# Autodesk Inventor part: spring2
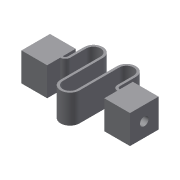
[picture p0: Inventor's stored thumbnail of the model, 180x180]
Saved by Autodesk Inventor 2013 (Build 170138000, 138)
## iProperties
Created: 2013-11
Part Number: spring2
Material: Generic
Document SubType Name: Modeling
Designer: Jonas
Density: 1 g/cm^3
Author: Jonas
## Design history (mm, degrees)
sketch "Sketch1"
  geometry: L1 (19, -5)-(10, -5); L2 (10, -5)-(10, 5); L3 (10, 5)-(19, 5); L4 (19, 5)-(19, -5); 2 further points
  constraints: 8 end point, 2 parallel, 1 horizontal, 1 horizontal alignment, 1 midpoint, 1 perpendicular
  dimensions: "d1" = 9 distance of L2.end L3.end; "d2" = 10 distance of L1.end L2.end; "d3" = 19 distance from line of L4 point (0, 0)
extrude "Extrusion1" new body sketch "Sketch1" distance "d4" = 10; taper "d5" = 0 deg
sketch "Sketch2"
  geometry: L1 (10, -5)-(19, -5) reference; L2 (19, -5)-(19, 5) reference; L3 (19, 5)-(10, 5) reference; L4 (10, 5)-(10, -5) reference; L5 (10, 0.4)-(10, -0.4); L6 (9.062, 1.338)-(9.062, 7); L7 (2.487, 7)-(2.487, -7); L8 (8.262, 1.338)-(8.262, 7); L9 (3.287, 7)-(3.287, -7); L10 (0, -10.287)-(0, -9.487); L11 (0, 0)-(0, 11.396); A1 r 0.938 centre (10, 1.338) between (9.062, 1.338) and (10, 0.4); A2 r 3.287 centre (5.775, 7) between (9.062, 7) and (2.487, 7); A3 r 2.487 centre (0, -7) between (0, -9.487) and (2.487, -7); A4 r 1.738 centre (10, 1.338) between (8.262, 1.338) and (10, -0.4); A5 r 2.487 centre (5.775, 7) between (8.262, 7) and (3.287, 7); A6 r 3.287 centre (0, -7) between (0, -10.287) and (3.287, -7); 3 further points
  constraints: 14 end point, 12 point on circle, 8 tangent, 6 centre point, 5 parallel, 4 coincident, 4 line through centre, 2 midpoint, 2 vertical, 1 collinear, 1 equal radius, 1 point on line, 1 vertical alignment, 1 other
  dimensions: "d6" = 0.8 distance of L5.start L5.end; "d11" = 7 vertical distance of A2.centre point (0, 0); "d12" = 7 distance of A3.centre point (0, 0) (= d11); "d14" = 0.8 distance between parallel lines of L6 L8
extrude "Extrusion2" join sketch "Sketch2" stored distance "d18" = 10; taper "d19" = 0 deg
sketch "Sketch3"
  geometry: C1 r 1.5 at (-5, 5); 1 further point
  constraints: 1 centre point
  dimensions: "d20" = 3 diameter of C1
extrude "Extrusion3" cut sketch "Sketch3" distance "d21" = 6; taper "d22" = 0 deg
mirror "Mirror1"
body "Solid1"
node "Projected Loop1"
